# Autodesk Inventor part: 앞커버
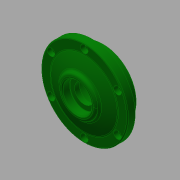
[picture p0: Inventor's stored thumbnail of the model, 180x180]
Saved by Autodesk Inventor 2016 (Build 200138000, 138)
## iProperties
Created: 2016-05
Part Number: 앞커버
Document SubType Name: Modeling
Designer: mduedu
Density: 2.71 g/cm^3
Material: 알루미늄 6061
Appearance: 진녹색
Author: mduedu
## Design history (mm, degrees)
sketch "스케치1"
  geometry: C1 r 35 at (0, 0); C2 r 45 at (0, 0); 1 further point
  constraints: 2 centre point, 2 coincident
  dimensions: "d33" = 90 diameter of C2; "d34" = 70 diameter of C1
extrude "돌출1" new body sketch "스케치1" distance "d0" = 8; taper "d1" = 0 deg
extrude "돌출2" join sketch "스케치1" distance "d2" = 8; taper "d3" = 0 deg; dims "d35" = 12, "d36" = 0
sketch "스케치5"
  geometry: L1 (-45, 8)-(45, 8) reference; L2 (0, 0)-(0, 15); L3 (-45, 0)-(45, 0) reference; L4 (35, 8)-(0, 8); A1 r 91 centre (0, -76) between (35, 8) and (0, 15)
  constraints: 4 end point, 3 point on line, 2 point on circle, 1 centre point, 1 midpoint, 1 perpendicular
  dimensions: "d37" = 35 distance from line of L2 L4.start; "d39" = 7 distance from line of L1 L2.end
revolve "회전2" sketch "스케치5" stored, may be unused: angle "d40" = 90 deg
node "작업 평면1"
sketch "스케치6"
  geometry: C1 r 20 at (0, 0); 1 further point
  constraints: 1 centre point, 1 coincident
  dimensions: "d42" = 40 diameter of C1
extrude "돌출4" join sketch "스케치6" stored distance "d43" = 10; taper "d44" = 0 deg
sketch "스케치4"
  geometry: L1 (0, -12)-(0, 16); L2 (-20, -12)-(-20, 0); L3 (-20, 0)-(-15, 0); L4 (-15, 0)-(-15, 3); L5 (-15, 3)-(-10, 3); L6 (-10, 3)-(-10, 8); L7 (-10, 8)-(-15, 8); L8 (-15, 8)-(-15, 16); L9 (35, -12)-(-35, -12) reference; L10 (-20, 16)-(20, 16) reference; 1 further point
  constraints: 16 end point, 6 parallel, 3 point on line, 2 midpoint, 1 perpendicular, 1 vertical
  dimensions: "d15" = 40 diameter of L2 L1; "d16" = 30 diameter of L8 L1; "d18" = 12 distance of L2.start L2.end; "d19" = 3 distance of L3.end L4.end; "d20" = 30 diameter of L4 L1; "d21" = 20 diameter of L6 L1; "d45" = 8 distance of L7.end L8.end
revolve "회전1" sketch "스케치4" stored, may be unused: angle "d22" = 90 deg
fillet "모깎기2" dims "d23" = 3
fillet "모깎기3" dims "d24" = 0.3
chamfer "모따기2" distance "d46" = 1; stored, may be unused: second distance "d47" = 2, angle "d48" = 45 deg
fillet "모깎기4" dims "d49" = 3
fillet "모깎기5" dims "d50" = 3
fillet "모깎기6" dims "d51" = 1
sketch "스케치7" dims "d52" = 80
  geometry: C1 r 35.595 at (0, 0) reference; C2 r 44 at (0, 0) reference; 7 further points
  constraints: 2 vertical alignment, 1 coincident, 9 other
  dimensions: "d55" = 360 deg dimension on C1.centre point (0, 40) (derived)
sketch "스케치8"
  geometry: 6 further points
  constraints: 6 other
hole "구멍2" sketch "스케치8" at (-34.641, 20), (-34.641, -20), (0, -40), (34.641, -20), (34.641, 20), (0, 40) diameter "d57" = 4.5; stored, may be unused: countersink angle "d61" = 90 deg, drill point angle "d63" = 0 deg; dims "d58" = 6, "d59" = 8, "d60" = 4.6, "d62" = 8
node "솔리드1"
other parameters: "d41" = 8
